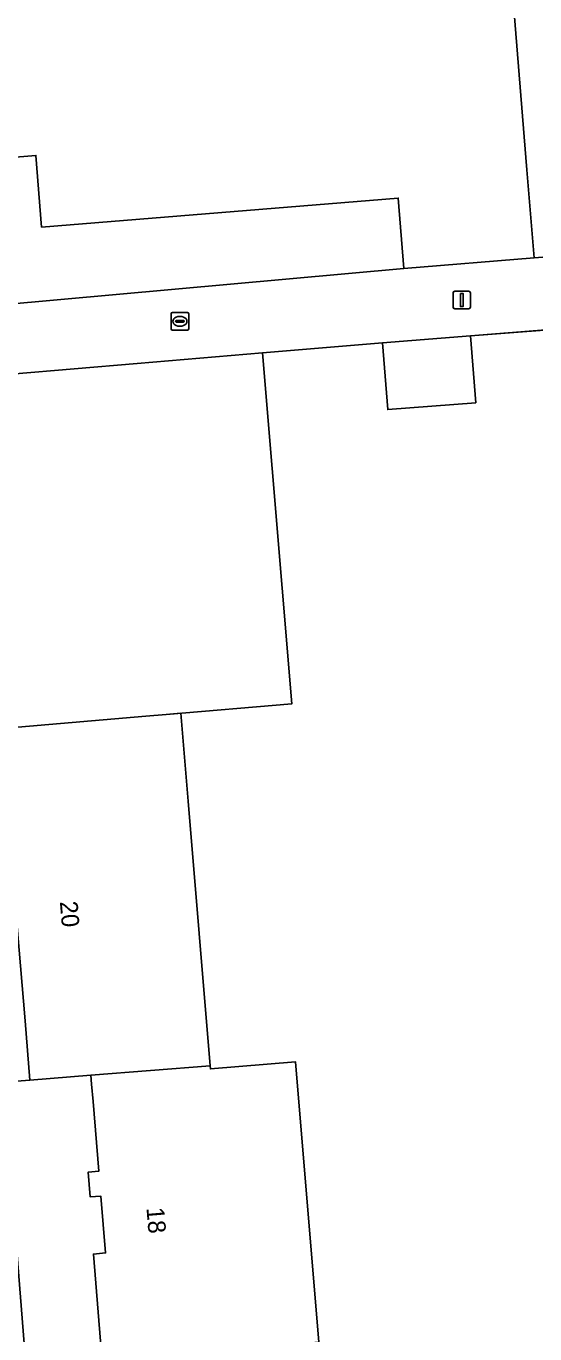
# Model space of a CAD drawing. Extents: x 157793 to 159380, y 380877 to 382313.
# Drawn here: x 158152.9 to 158181.7, y 381260.3 to 381334.5 of the extents above; entities that cross this region are included whole.
import ezdxf

# ---------------------------------------------------------------- set-up
doc = ezdxf.new("R2010")
doc.units = 0
for name, color, linetype in [('IMGEO_Erf', 7, 'Continuous'), ('IMGEO_Kolk', 7, 'Continuous'), ('IMGEO_Lichtmast', 7, 'Continuous'), ('IMGEO_Muur', 7, 'Continuous'), ('IMGEO_Pand', 7, 'Continuous'), ('IMGEO_Pand_nummerreeks', 7, 'Continuous'), ('IMGEO_Voetpad_open', 7, 'Continuous')]:
    doc.layers.add(name, color=color, linetype=linetype)

msp = doc.modelspace()

# ---------------------------------------------------------------- linework, layer by layer
at = {"layer": 'IMGEO_Erf'}
for points in [[(158124.465, 381365.343), (158154.395, 381367.776), (158156.049, 381347.419), (158179.429, 381349.319), (158181.297, 381326.328), (158181.702, 381321.344), (158200.589, 381322.782), (158204.145, 381323.053), (158210.221, 381323.515), (158205.204, 381387.515)], [(158121.637, 381341.71), (158131.815, 381325.934), (158131.903, 381325.796), (158135.738, 381319.823), (158137.196, 381317.545), (158148.179, 381318.378), (158174.322, 381320.744), (158173.998, 381324.728), (158153.786, 381323.086), (158153.466, 381327.148), (158144.954, 381326.456), (158144.428, 381332.904), (158138.148, 381332.392), (158137.068, 381345.666)], [(158184.505, 381317.435), (158178.098, 381316.915), (158178.391, 381313.127), (158173.405, 381312.741), (158173.112, 381316.529), (158166.317, 381315.953), (158167.979, 381296.063), (158160.857, 381295.455), (158161.69, 381295.523), (158162.102, 381290.54), (158163.343, 381275.531), (158163.357, 381275.358), (158168.188, 381275.758), (158169.503, 381259.859)], [(158157.27, 381258.287), (158156.726, 381264.864), (158157.414, 381264.921), (158157.147, 381268.15), (158156.548, 381268.101), (158156.433, 381269.506), (158157.03, 381269.555), (158156.705, 381273.503), (158156.623, 381274.491), (158156.582, 381274.995), (158153.133, 381274.721), (158151.631, 381274.599), (158153.242, 381254.297)]]:
    msp.add_lwpolyline(points, dxfattribs=at)
at = {"layer": 'IMGEO_Kolk'}
for p, q in [((158161.127, 381317.318), (158161.127, 381318.17)), ((158161.202, 381318.244), (158162.054, 381318.244)), ((158161.615, 381318.024), (158161.64, 381318.024)), ((158162.128, 381318.17), (158162.128, 381317.318)), ((158162.054, 381317.244), (158161.202, 381317.244)), ((158161.386, 381317.738), (158161.386, 381317.75)), ((158161.824, 381317.701), (158161.426, 381317.701)), ((158161.429, 381317.787), (158161.827, 381317.787)), ((158161.638, 381317.464), (158161.613, 381317.464)), ((158161.87, 381317.75), (158161.87, 381317.738))]:
    msp.add_line(p, q, dxfattribs=at)
for points in [[(158161.127, 381317.318), (158161.127, 381318.17)], [(158161.202, 381318.244), (158162.054, 381318.244)], [(158162.128, 381318.17), (158162.128, 381317.318)], [(158162.054, 381317.244), (158161.202, 381317.244)]]:
    msp.add_lwpolyline(points, dxfattribs=at)
for centre, radius, start, end in [((158161.204, 381318.168), 0.0765, 91.55205, 178.44795), ((158161.204, 381318.168), 0.0765, 91.55205, 178.44795), ((158162.052, 381318.168), 0.0765, 1.55205, 88.44795), ((158162.052, 381318.168), 0.0765, 1.55205, 88.44795), ((158161.204, 381317.32), 0.0765, 181.55205, 268.44795), ((158161.204, 381317.32), 0.0765, 181.55205, 268.44795), ((158161.426, 381317.747), 0.0403, 85.87752, 175.75265), ((158161.423, 381317.737), 0.0366, 178.93798, 274.71019), ((158161.827, 381317.744), 0.043, 264.86636, 352.45326), ((158161.831, 381317.749), 0.0386, 1.73085, 96.63898), ((158162.052, 381317.32), 0.0765, 271.55205, 358.44795), ((158162.052, 381317.32), 0.0765, 271.55205, 358.44795)]:
    msp.add_arc(centre, radius, start, end, dxfattribs=at)
for centre, major_axis, ratio, start_param, end_param in [((158161.614, 381317.744), (-0.387, 0.002), 0.722429, 4.712389, 7.853982), ((158161.639, 381317.744), (-0.39, 0.002), 0.717154, 1.570796, 4.712389)]:
    msp.add_ellipse(centre, major_axis=major_axis, ratio=ratio, start_param=start_param, end_param=end_param, dxfattribs=at)
at = {"layer": 'IMGEO_Lichtmast'}
for p, q in [((158177.106, 381318.553), (158177.106, 381319.353)), ((158177.106, 381319.353), (158177.106, 381318.553)), ((158177.206, 381319.453), (158177.996, 381319.453)), ((158177.996, 381319.453), (158177.206, 381319.453)), ((158178.096, 381319.353), (158178.096, 381318.553)), ((158178.096, 381318.553), (158178.096, 381319.353)), ((158177.996, 381318.453), (158177.206, 381318.453)), ((158177.206, 381318.453), (158177.996, 381318.453))]:
    msp.add_line(p, q, dxfattribs=at)
msp.add_lwpolyline([(158177.526, 381319.328), (158177.676, 381319.328), (158177.676, 381318.578), (158177.526, 381318.578), (158177.526, 381319.328)], dxfattribs=at)
for centre, start, end in [((158177.206, 381319.353), 90, 180), ((158177.206, 381319.353), 90, 180), ((158177.996, 381319.353), 0, 90), ((158177.996, 381319.353), 360, 90), ((158177.206, 381318.553), 180, 270), ((158177.206, 381318.553), 180, 270), ((158177.996, 381318.553), 270, 0), ((158177.996, 381318.553), 270, 0)]:
    msp.add_arc(centre, 0.1, start, end, dxfattribs=at)
at = {"layer": 'IMGEO_Muur'}
for points in [[(158200.589, 381322.782), (158181.702, 381321.344)], [(158184.506, 381317.41), (158178.098, 381316.915)], [(158173.112, 381316.529), (158166.317, 381315.953)]]:
    msp.add_lwpolyline(points, dxfattribs=at)
at = {"layer": 'IMGEO_Pand'}
for points in [[(158137.068, 381345.666), (158138.148, 381332.392), (158144.428, 381332.904), (158144.954, 381326.456), (158153.466, 381327.148), (158153.786, 381323.086), (158173.998, 381324.728), (158174.322, 381320.744), (158181.702, 381321.344), (158181.297, 381326.328), (158179.429, 381349.319), (158156.049, 381347.419), (158156.069, 381347.169)], [(158173.112, 381316.529), (158173.405, 381312.741), (158178.391, 381313.127), (158178.098, 381316.915)], [(158166.317, 381315.953), (158159.212, 381315.351), (158148.478, 381314.442), (158148.612, 381312.832), (158148.658, 381312.275), (158149.209, 381305.365), (158149.969, 381295.114), (158150.013, 381294.53), (158159.691, 381295.356), (158160.857, 381295.455), (158167.979, 381296.063)], [(158162.102, 381290.54), (158161.69, 381295.523), (158160.857, 381295.455), (158159.691, 381295.356), (158150.013, 381294.53), (158150.26, 381291.187), (158150.313, 381290.478), (158151.82, 381290.603), (158152.182, 381286.221), (158152.431, 381283.212), (158152.855, 381278.087), (158153.133, 381274.721), (158156.582, 381274.995), (158163.343, 381275.531)], [(158163.343, 381275.531), (158156.582, 381274.995), (158156.623, 381274.491), (158156.705, 381273.503), (158157.03, 381269.555), (158156.433, 381269.506), (158156.548, 381268.101), (158157.147, 381268.15), (158157.414, 381264.921), (158156.726, 381264.864), (158157.27, 381258.287), (158157.957, 381258.343), (158157.911, 381258.901), (158162.895, 381259.313), (158169.503, 381259.859), (158168.188, 381275.758), (158163.357, 381275.358)]]:
    msp.add_lwpolyline(points, close=True, dxfattribs=at)
at = {"layer": 'IMGEO_Voetpad_open'}
msp.add_lwpolyline([(158200.897, 381318.677), (158200.589, 381322.782), (158181.702, 381321.344), (158174.322, 381320.744), (158148.179, 381318.378), (158148.478, 381314.442), (158159.212, 381315.351), (158166.317, 381315.953), (158173.112, 381316.529), (158178.098, 381316.915), (158184.505, 381317.435), (158192.346, 381318.048)], close=True, dxfattribs=at)
msp.add_lwpolyline([(158148.754, 381276.589), (158147.113, 381274.618), (158146.913, 381274.316), (158151.631, 381274.599), (158153.133, 381274.721), (158152.855, 381278.087), (158152.431, 381283.212), (158152.182, 381286.221)], dxfattribs=at)

# ---------------------------------------------------------------- texts
at = {"layer": 'IMGEO_Pand_nummerreeks'}
for s, p in [('20', (158154.825, 381284.839)), ('18', (158159.732, 381267.473))]:
    msp.add_text(s, height=1, rotation=274.72669, dxfattribs=at).set_placement(p)

doc.saveas('drawing.dxf')
